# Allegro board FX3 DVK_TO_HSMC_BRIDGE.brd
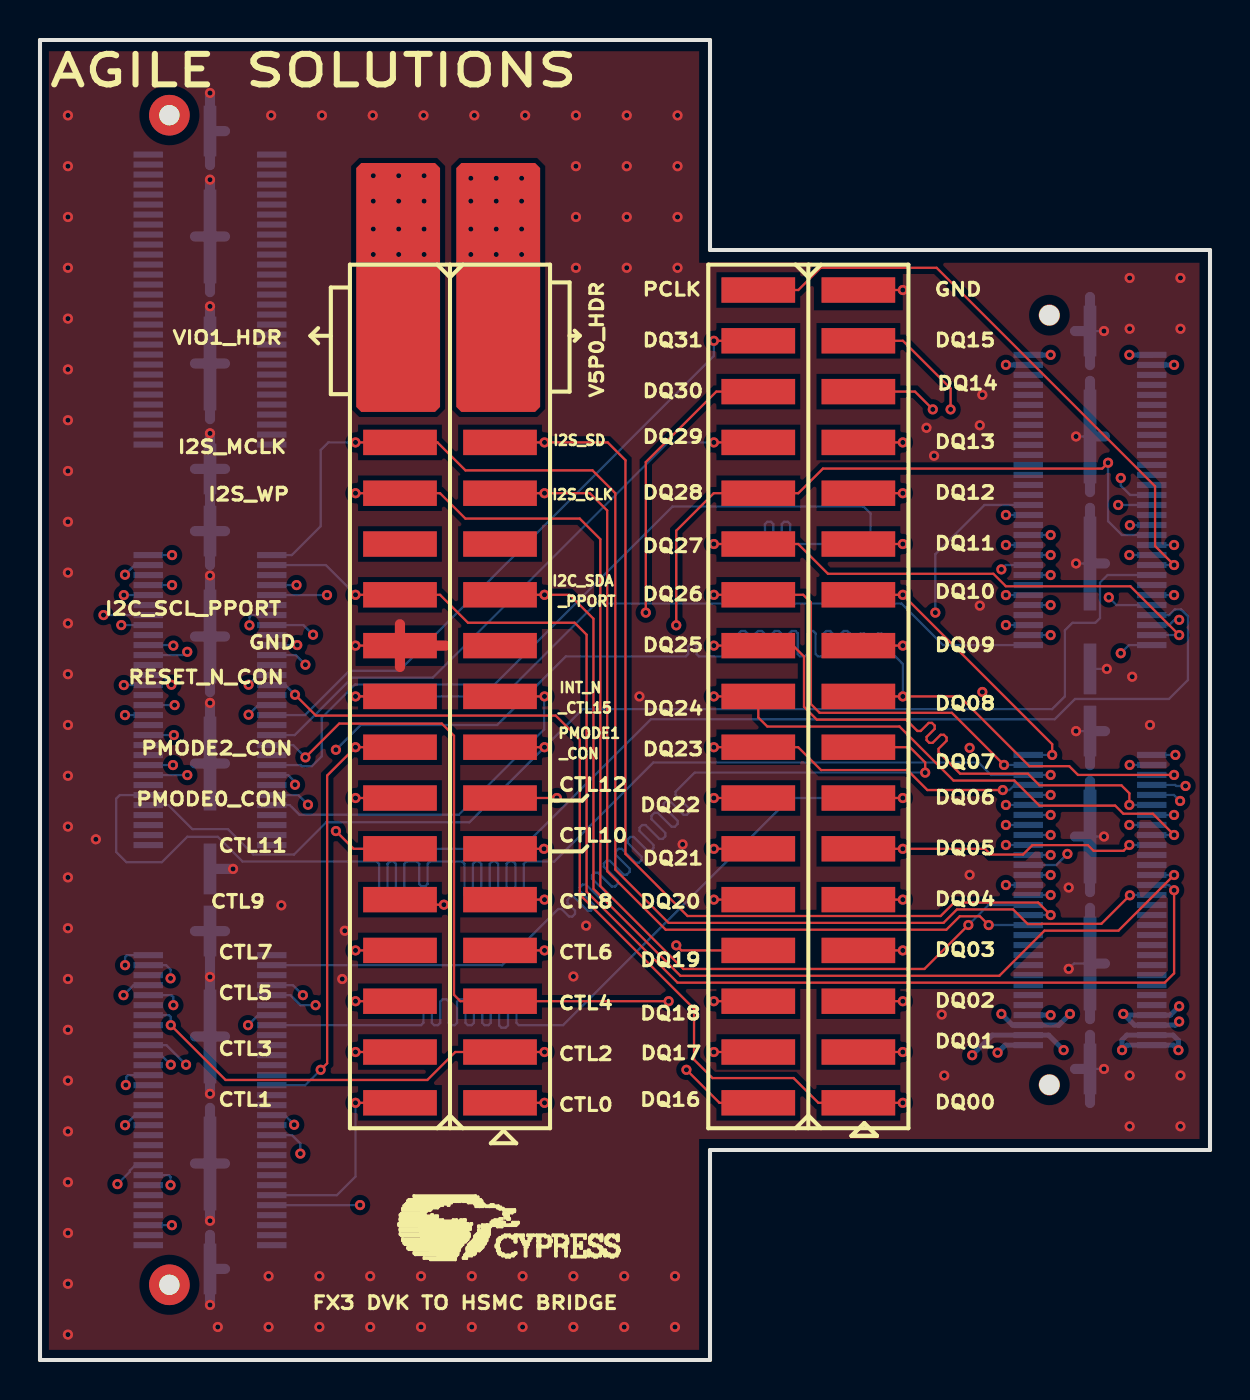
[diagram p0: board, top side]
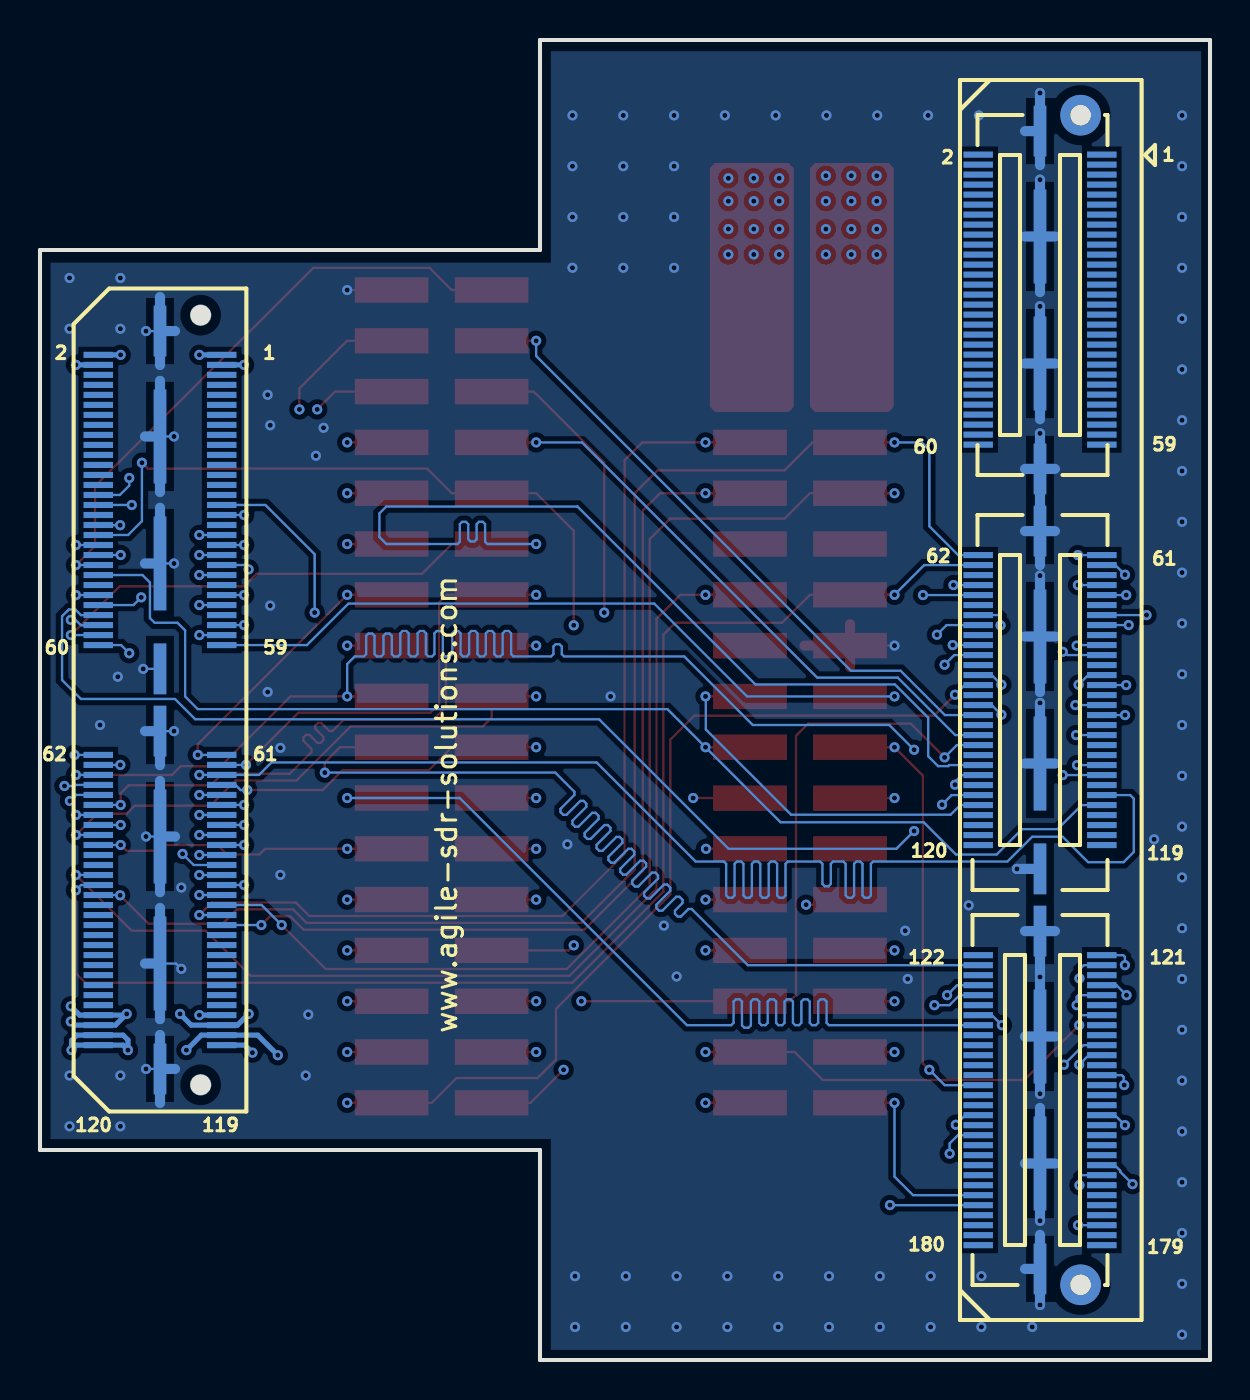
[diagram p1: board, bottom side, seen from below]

Outline 58.5 x 66 mm; copper layers: TOP, L02_GND1, L03_SIG1, L04_SIG2, L05_PWR1, BOTTOM. Coordinates in mm from the lower left corner of the outline.
Outline path: 0,66 0,0 33.5,0 33.5,10.5 58.5,10.5 58.5,55.5 33.5,55.5 33.5,66 0,66

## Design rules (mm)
net group DATA1: nets DQ0 DQ1 DQ2 DQ3 DQ4 DQ5 DQ6 DQ7 DQ8 DQ9 DQ10 DQ11 DQ12 DQ13 DQ14 DQ15 DQ16 DQ17 DQ18 DQ19 DQ20 DQ21 DQ22 DQ23 DQ24 DQ25 DQ26 DQ27 DQ28 DQ29 DQ30 DQ31 PCLK

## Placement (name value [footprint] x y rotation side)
J5  95278-101-34LF  [BERG_2X17_SMD]  38.42 29.37 0 top
J6  95278-101-34LF  [BERG_2X17_SMD]  20.5 29.37 0 top
J7  HSMC CONNECTOR  [CON_180P_19]  8.5 33 270 bottom
J8  QTH120_CONN  [CONN_QTH-060-01-L-D-A]  52.5 33 270 bottom

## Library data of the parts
J5 = HEADER 20x2/SM_1
J6 = HEADER 20x2/SM_0
J7 = HSMC CONNECTOR_0
J8 = QTH120_CONN_3

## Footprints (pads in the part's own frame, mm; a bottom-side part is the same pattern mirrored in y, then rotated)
BERG_2X17_SMD
  rect 3.683x1.27 smd: 1(2.502,-16.51) 2(-2.502,-16.51) 3(2.502,-13.97) 4(-2.502,-13.97) 5(2.502,-11.43) 6(-2.502,-11.43) 7(2.502,-8.89) 8(-2.502,-8.89) 9(2.502,-6.35) 10(-2.502,-6.35) 11(2.502,-3.81) 12(-2.502,-3.81) 13(2.502,-1.27) 14(-2.502,-1.27) 15(2.502,1.27) 16(-2.502,1.27) 17(2.502,3.81) 18(-2.502,3.81) 19(2.502,6.35) 20(-2.502,6.35) 21(2.502,8.89) 22(-2.502,8.89) 23(2.502,11.43) 24(-2.502,11.43) 25(2.502,13.97) 26(-2.502,13.97) 27(2.502,16.51) 28(-2.502,16.51) 29(2.502,19.05) 30(-2.502,19.05) 31(2.502,21.59) 32(-2.502,21.59) 33(2.502,24.13) 34(-2.502,24.13)
CON_180P_19
  round 2.032 hole 1.016 unplated: (-29.24,2.03) (29.24,2.03)
  rect 0.305x1.473 smd: 1(-27.269,3.09) 2(-27.269,-3.09) 3(-26.769,3.09) 4(-26.769,-3.09) 5(-26.269,3.09) 6(-26.269,-3.09) 7(-25.769,3.09) 8(-25.769,-3.09) 9(-25.269,3.09) 10(-25.269,-3.09) 11(-24.769,3.09) 12(-24.769,-3.09) 13(-24.269,3.09) 14(-24.269,-3.09) 15(-23.769,3.09) 16(-23.769,-3.09) 17(-23.269,3.09) 18(-23.269,-3.09) 19(-22.769,3.09) 20(-22.769,-3.09) 21(-22.269,3.09) 22(-22.269,-3.09) 23(-21.769,3.09) 24(-21.769,-3.09) 25(-21.269,3.09) 26(-21.269,-3.09) 27(-20.769,3.09) 28(-20.769,-3.09) 29(-20.269,3.09) 30(-20.269,-3.09) 31(-19.769,3.09) 32(-19.769,-3.09) 33(-19.269,3.09) 34(-19.269,-3.09) 35(-18.769,3.09) 36(-18.769,-3.09) 37(-18.269,3.09) 38(-18.269,-3.09) 39(-17.769,3.09) 40(-17.769,-3.09) 41(-17.269,3.09) 42(-17.269,-3.09) 43(-16.769,3.09) 44(-16.769,-3.09) 45(-16.269,3.09) 46(-16.269,-3.09) 47(-15.769,3.09) 48(-15.769,-3.09) 49(-15.269,3.09) 50(-15.269,-3.09) 51(-14.769,3.09) 52(-14.769,-3.09) 53(-14.269,3.09) 54(-14.269,-3.09) 55(-13.769,3.09) 56(-13.769,-3.09) 57(-13.269,3.09) 58(-13.269,-3.09) 59(-12.769,3.09) 60(-12.769,-3.09) 61(-7.247,3.09) 62(-7.247,-3.09) 63(-6.747,3.09) 64(-6.747,-3.09) 65(-6.247,3.09) 66(-6.247,-3.09) 67(-5.747,3.09) 68(-5.747,-3.09) 69(-5.247,3.09) 70(-5.247,-3.09) 71(-4.747,3.09) 72(-4.747,-3.09) 73(-4.247,3.09) 74(-4.247,-3.09) 75(-3.747,3.09) 76(-3.747,-3.09) 77(-3.247,3.09) 78(-3.247,-3.09) 79(-2.747,3.09) 80(-2.747,-3.09) 81(-2.247,3.09) 82(-2.247,-3.09) 83(-1.747,3.09) 84(-1.747,-3.09) 85(-1.247,3.09) 86(-1.247,-3.09) 87(-0.747,3.09) 88(-0.747,-3.09) 89(-0.247,3.09) 90(-0.247,-3.09) 91(0.253,3.09) 92(0.253,-3.09) 93(0.753,3.09) 94(0.753,-3.09) 95(1.253,3.09) 96(1.253,-3.09) 97(1.753,3.09) 98(1.753,-3.09) 99(2.253,3.09) 100(2.253,-3.09) 101(2.753,3.09) 102(2.753,-3.09) 103(3.253,3.09) 104(3.253,-3.09) 105(3.753,3.09) 106(3.753,-3.09) 107(4.253,3.09) 108(4.253,-3.09) 109(4.753,3.09) 110(4.753,-3.09) 111(5.253,3.09) 112(5.253,-3.09) 113(5.753,3.09) 114(5.753,-3.09) 115(6.253,3.09) 116(6.253,-3.09) 117(6.753,3.09) 118(6.753,-3.09) 119(7.253,3.09) 120(7.253,-3.09) 121(12.758,3.09) 122(12.758,-3.09) 123(13.258,3.09) 124(13.258,-3.09) 125(13.758,3.09) 126(13.758,-3.09) 127(14.258,3.09) 128(14.258,-3.09) 129(14.758,3.09) 130(14.758,-3.09) 131(15.258,3.09) 132(15.258,-3.09) 133(15.758,3.09) 134(15.758,-3.09) 135(16.258,3.09) 136(16.258,-3.09) 137(16.758,3.09) 138(16.758,-3.09) 139(17.258,3.09) 140(17.258,-3.09) 141(17.758,3.09) 142(17.758,-3.09) 143(18.258,3.09) 144(18.258,-3.09) 145(18.758,3.09) 146(18.758,-3.09) 147(19.258,3.09) 148(19.258,-3.09) 149(19.758,3.09) 150(19.758,-3.09) 151(20.258,3.09) 152(20.258,-3.09) 153(20.758,3.09) 154(20.758,-3.09) 155(21.258,3.09) 156(21.258,-3.09) 157(21.758,3.09) 158(21.758,-3.09) 159(22.258,3.09) 160(22.258,-3.09) 161(22.758,3.09) 162(22.758,-3.09) 163(23.258,3.09) 164(23.258,-3.09) 165(23.758,3.09) 166(23.758,-3.09) 167(24.258,3.09) 168(24.258,-3.09) 169(24.758,3.09) 170(24.758,-3.09) 171(25.258,3.09) 172(25.258,-3.09) 173(25.758,3.09) 174(25.758,-3.09) 175(26.258,3.09) 176(26.258,-3.09) 177(26.758,3.09) 178(26.758,-3.09) 179(27.258,3.09) 180(27.258,-3.09)
  rect 4.699x0.635 smd: 181(-16.825,0) 184(-3.175,0) 185(3.175,0) 188(16.825,0) 189(23.175,0) 192(-23.175,0)
  rect 2.54x0.635 smd: 182(-11.555,0) 183(-8.445,0) 186(8.445,0) 187(11.555,0) 190(28.445,0) 191(-28.445,0)
CONN_QTH-060-01-L-D-A
  round 1.067 hole 1.016 unplated: (-19.241,2.032) (19.241,2.032)
  rect 0.305x1.473 smd: 1(-17.257,3.086) 2(-17.257,-3.086) 3(-16.756,3.086) 4(-16.756,-3.086) 5(-16.256,3.086) 6(-16.256,-3.086) 7(-15.756,3.086) 8(-15.756,-3.086) 9(-15.255,3.086) 10(-15.255,-3.086) 11(-14.755,3.086) 12(-14.755,-3.086) 13(-14.255,3.086) 14(-14.255,-3.086) 15(-13.754,3.086) 16(-13.754,-3.086) 17(-13.254,3.086) 18(-13.254,-3.086) 19(-12.753,3.086) 20(-12.753,-3.086) 21(-12.253,3.086) 22(-12.253,-3.086) 23(-11.753,3.086) 24(-11.753,-3.086) 25(-11.252,3.086) 26(-11.252,-3.086) 27(-10.752,3.086) 28(-10.752,-3.086) 29(-10.251,3.086) 30(-10.251,-3.086) 31(-9.751,3.086) 32(-9.751,-3.086) 33(-9.251,3.086) 34(-9.251,-3.086) 35(-8.75,3.086) 36(-8.75,-3.086) 37(-8.25,3.086) 38(-8.25,-3.086) 39(-7.749,3.086) 40(-7.749,-3.086) 41(-7.249,3.086) 42(-7.249,-3.086) 43(-6.749,3.086) 44(-6.749,-3.086) 45(-6.248,3.086) 46(-6.248,-3.086) 47(-5.748,3.086) 48(-5.748,-3.086) 49(-5.248,3.086) 50(-5.248,-3.086) 51(-4.747,3.086) 52(-4.747,-3.086) 53(-4.247,3.086) 54(-4.247,-3.086) 55(-3.747,3.086) 56(-3.747,-3.086) 57(-3.246,3.086) 58(-3.246,-3.086) 59(-2.746,3.086) 60(-2.746,-3.086) 61(2.746,3.086) 62(2.746,-3.086) 63(3.246,3.086) 64(3.246,-3.086) 65(3.747,3.086) 66(3.747,-3.086) 67(4.247,3.086) 68(4.247,-3.086) 69(4.747,3.086) 70(4.747,-3.086) 71(5.248,3.086) 72(5.248,-3.086) 73(5.748,3.086) 74(5.748,-3.086) 75(6.248,3.086) 76(6.248,-3.086) 77(6.749,3.086) 78(6.749,-3.086) 79(7.249,3.086) 80(7.249,-3.086) 81(7.749,3.086) 82(7.749,-3.086) 83(8.25,3.086) 84(8.25,-3.086) 85(8.75,3.086) 86(8.75,-3.086) 87(9.251,3.086) 88(9.251,-3.086) 89(9.751,3.086) 90(9.751,-3.086) 91(10.251,3.086) 92(10.251,-3.086) 93(10.752,3.086) 94(10.752,-3.086) 95(11.252,3.086) 96(11.252,-3.086) 97(11.753,3.086) 98(11.753,-3.086) 99(12.253,3.086) 100(12.253,-3.086) 101(12.753,3.086) 102(12.753,-3.086) 103(13.254,3.086) 104(13.254,-3.086) 105(13.754,3.086) 106(13.754,-3.086) 107(14.255,3.086) 108(14.255,-3.086) 109(14.755,3.086) 110(14.755,-3.086) 111(15.255,3.086) 112(15.255,-3.086) 113(15.756,3.086) 114(15.756,-3.086) 115(16.256,3.086) 116(16.256,-3.086) 117(16.756,3.086) 118(16.756,-3.086) 119(17.257,3.086) 120(17.257,-3.086)
  rect 2.54x0.635 smd: 121(-18.447,0) 124(-1.556,0) 125(1.556,0) 128(18.447,0)
  rect 4.699x0.635 smd: 122(-13.176,0) 123(-6.826,0) 126(6.826,0) 127(13.176,0)

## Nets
GND2: J5.33 J6.20 J7.181 J7.182 J7.183 J7.184 J7.185 J7.186 J7.187 J7.188 J7.189 J7.190 J7.191 J7.192 J8.121 J8.122 J8.123 J8.124 J8.125 J8.126 J8.127 J8.128
V5P0_HDR: J6.29 J6.31 J6.33 J8.113 J8.114 J8.115 J8.116
CTL0: J6.1 J7.158 J8.33
CTL1: J6.2 J7.170 J8.51
CTL2: J6.3 J7.133 J8.55
CTL3: J6.4 J7.154 J8.31
CTL4: J6.5 J7.100 J8.60
CTL5: J6.6 J7.163 J8.39
CTL6: J6.7 J7.141 J8.45
CTL7: J6.8 J7.165 J8.37
CTL8: J6.9 J7.139 J8.49
CTL9: J6.10 J7.153 J8.41
CTL10: J6.11 J7.145 J8.43
CTL11: J6.12 J7.110 J8.54
CTL12: J6.13 J7.129 J8.57
DQ0: J5.1 J7.88 J8.68
DQ1: J5.3 J7.80 J8.74
DQ2: J5.5 J7.76 J8.76
DQ3: J5.7 J7.86 J8.70
DQ4: J5.9 J7.172 J8.50
DQ5: J5.11 J7.70 J8.80
DQ6: J5.13 J7.136 J8.32
DQ7: J5.15 J7.124 J8.42
DQ8: J5.17 J7.92 J8.66
DQ9: J5.19 J7.69 J8.89
DQ10: J5.21 J7.123 J8.61
DQ11: J5.23 J7.85 J8.79
DQ12: J5.25 J7.97 J8.71
DQ13: J5.27 J7.81 J8.81
DQ14: J5.29 J7.109 J8.65
DQ15: J5.31 J7.79 J8.83
DQ16: J5.2 J7.106 J8.56
DQ17: J5.4 J7.75 J8.85
DQ18: J5.6 J7.93 J8.73
DQ19: J5.8 J7.73 J8.87
DQ20: J5.10 J7.87 J8.77
DQ21: J5.12 J7.91 J8.75
DQ22: J5.14 J7.103 J8.69
DQ23: J5.16 J7.105 J8.67
DQ24: J5.18 J7.74 J8.78
DQ25: J5.20 J7.82 J8.72
DQ26: J5.22 J7.121 J8.63
DQ27: J5.24 J7.104 J8.58
DQ28: J5.26 J7.130 J8.38
DQ29: J5.28 J7.98 J8.62
DQ30: J5.30 J7.128 J8.40
DQ31: J5.32 J7.94 J8.64
I2C_SCL_PPORT: J6.22 J7.64 J8.88
I2C_SDA_PPORT: J6.21 J7.68 J8.86
I2S-MCLK: J6.28 J7.62 J8.90
I2S_CLK: J6.25 J7.61 J8.95
I2S_SD: J6.27 J7.63 J8.93
I2S_WP: J6.26 J7.67 J8.91
INT_N_CTL15: J6.17 J7.112 J8.52
PCLK: J5.34 J7.175 J8.44
PMODE0_CON: J6.14 J7.134 J8.36
PMODE1_CON: J6.15 J7.111 J8.46
PMODE2_CON: J6.16 J7.148 J8.30
RESET_N_CON: J6.18 J7.127 J8.59
VIO1_HDR: J6.30 J6.32 J6.34 J8.1 J8.2 J8.3 J8.4 J8.117 J8.118 J8.119 J8.120

Pads without a net: J6 19 23 24; J7 1 2 3 4 5 6 7 8 9 10 11 12 13 14 15 16 17 18 19 20 21 22 23 24 25 26 27 28 29 30 31 32 33 34 35 36 37 38 39 40 41 42 43 44 45 46 47 48 49 50 51 52 53 54 55 56 57 58 59 60 65 66 71 72 77 78 83 84 89 90 95 96 99 101 102 107 108 113 114 115 116 117 118 119 120 122 125 126 131 132 135 137 138 140 142 143 144 146 147 149 150 151 152 155 156 157 159 160 161 162 164 166 167 168 169 171 173 174 176 177 178 179 180; J8 5 6 7 8 9 10 11 12 13 14 15 16 17 18 19 20 21 22 23 24 25 26 27 28 29 34 35 47 48 53 82 84 92 94 96 97 98 99 100 101 102 103 104 105 106 107 108 109 110 111 112

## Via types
v1: diameter 0.508, hole 0.254, TOP to BOTTOM, 308 vias

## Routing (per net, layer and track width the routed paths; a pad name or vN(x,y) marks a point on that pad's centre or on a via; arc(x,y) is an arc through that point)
GND2: length 111.8
  TOP w0.114: J6.20 v1(15.78,35.72) ; J5.33 v1(43.14,53.5)
  TOP w0.508: J6.20 20.27,35.72 ; J6.20 18,34.65 ; J6.20 18,36.79
  BOTTOM w0.114: J8.124 v1(53.34,34.56) ; J8.128 v1(53.2,14.55) ; J8.123 v1(51.8,39.83) ; v1(51.43,19.56) 51.7,19.82 J8.127 ; J8.125 v1(51.8,31.44) ; J8.126 v1(53.2,26.17) ; J8.122 v1(51.8,46.18) ; J8.121 v1(53.2,51.45)
  BOTTOM w0.508: 8.5,59.74 J7.191 ; J7.191 v1(8.5,63.35) ; J7.191 9.25,61.45 ; 7.75,9.82 J7.189 ; J7.189 v1(8.5,6.96) ; J7.189 8.5,12.61 ; J7.189 9.25,9.82 ; 52.5,49.74 J8.121 ; J8.121 51.75,51.45 ; J8.121 52.5,53.15 ; J7.190 9.25,4.55 ; J7.190 8.5,6.26 ; J7.190 v1(8.5,2.75) ; 52.5,23.39 J8.126 ; J8.126 52.5,28.96 ; J8.126 51.75,26.17 ; 52.5,17.04 J8.127 ; J8.127 53.25,19.82 ; J8.127 52.5,22.61 ; 7.75,36.17 J7.184 ; J7.184 8.5,33.39 ; J7.184 9.25,36.17 ; J7.184 v1(8.5,39.22) ; 8.5,53.39 J7.192 ; J7.192 v1(8.5,59.02) ; J7.192 9.25,56.18 ; J7.192 7.75,56.18 ; 7.75,41.45 J7.183 ; J7.183 9.25,41.45 ; J7.183 8.5,39.74 ; J7.183 J7.182 ; 52.5,43.39 J8.122 ; J8.122 52.5,48.96 ; J8.122 53.25,46.18 ; J7.185 v1(8.5,32.85) ; J7.185 9.25,29.82 ; J7.185 7.75,29.82 ; J7.182 9.25,44.56 ; J7.182 v1(8.5,46.33) ; J7.182 7.75,44.56 ; 8.5,47.04 J7.181 ; J7.181 9.25,49.83 ; J7.181 v1(8.5,52.68) ; J7.181 7.75,49.83 ; 51.75,14.55 J8.128 ; J8.128 52.5,16.26 ; J8.128 52.5,12.85 ; 7.75,21.44 J7.187 ; J7.187 9.25,21.44 ; J7.187 v1(8.5,19.15) ; J7.188 9.25,16.17 ; J7.188 8.5,18.96 ; J7.188 7.75,16.17 ; J7.188 v1(8.5,13.31) ; 53.25,39.83 J8.123 52.5,42.61 ; v1(9.65,24.55) J7.186 ; 52.5,29.74 J8.125 53.25,31.44
  vias: v1(1.4,62.23) v1(1.4,59.69) v1(1.4,57.15) v1(1.4,54.61) v1(1.4,52.07) v1(1.4,49.53) v1(1.4,46.99) v1(1.4,44.45) v1(1.4,41.91) v1(1.4,39.37) v1(1.4,36.83) v1(1.4,34.29) v1(1.4,31.75) v1(1.4,29.21) v1(1.4,26.67) v1(1.4,24.13) v1(1.4,21.59) v1(1.4,19.05) v1(1.4,16.51) v1(1.4,13.97) v1(1.4,11.43) v1(1.4,8.89) v1(1.4,6.35) v1(1.4,3.81) v1(1.4,1.27) v1(2.79,26.04) v1(8.89,1.65) v1(11.43,4.19) v1(11.43,1.65) v1(11.56,62.23) v1(12.06,22.73) v1(13.97,4.19) v1(13.97,1.65) v1(14.1,62.23) v1(15.11,19.05) v1(15.24,21.46) v1(16.51,4.19) v1(16.51,1.65) v1(16.64,62.23) v1(19.05,4.19) v1(19.05,1.65) v1(19.18,62.23) v1(21.59,4.19) v1(21.59,1.65) v1(21.72,62.23) v1(24.13,4.19) v1(24.13,1.65) v1(24.26,62.23) v1(26.67,19.18) v1(26.67,4.19) v1(26.67,1.65) v1(26.8,62.23) v1(26.8,59.69) v1(26.8,57.15) v1(26.8,54.61) v1(27.3,21.72) v1(29.21,4.19) v1(29.21,1.65) v1(29.34,62.23) v1(29.34,59.69) v1(29.34,57.15) v1(29.34,54.61) v1(29.97,33.18) v1(31.75,4.19) v1(31.75,1.65) v1(31.88,62.23) v1(31.88,59.69) v1(31.88,57.15) v1(31.88,54.61) v1(32.13,25.78) v1(44.32,46.61) v1(44.7,45.21) v1(45.08,17.27) v1(45.21,14.22) v1(46.48,30.61) v1(46.48,24.26) v1(46.99,46.74) v1(46.99,37.72) v1(47.12,48.26) v1(47.12,33.4) v1(51.43,23.62) v1(54.48,54.1) v1(54.48,51.56) v1(54.48,14.22) v1(54.48,11.68) v1(54.61,34.16) v1(55.5,31.75) v1(57.02,54.1) v1(57.02,51.56) v1(57.02,14.22) v1(57.02,11.68)
V5P0_HDR: length 11
  BOTTOM w0.254: 54.22,17.24 54.73,16.74 J8.116 56.78,16.74 v1(56.96,16.92) ; 54.22,17.24 v1(54.17,17.3) ; 54.22,17.24 J8.114 56.52,17.24 v1(56.96,17.68) ; v1(48.07,17.3) 48.63,16.74 J8.115 50.94,16.74 v1(51.5,17.3) ; J8.113 v1(50.53,17.24)
  vias: v1(21.54,59.09) v1(21.54,57.94) v1(21.54,56.55) v1(21.54,55.28) v1(22.81,59.09) v1(22.81,57.94) v1(22.81,56.55) v1(22.81,55.28) v1(24.08,59.09) v1(24.08,57.94) v1(24.08,56.55) v1(24.08,55.28)
CTL0: length 74.3
  TOP w0.114: J6.1 v1(25.22,12.86)
  L03_SIG1 w0.114: v1(25.22,12.86) 22.68,10.32 v1(13.02,10.32)
  L04_SIG2 w0.114: v1(48.3,42.25) 51.82,42.25 54.38,39.69 54.65,39.69 54.91,39.43 54.91,38.06 53,36.15 52.99,36.15 48.08,31.24 41.24,31.24 39.18,29.17 30.73,29.17 29.65,28.1 29.65,17.29 v1(25.22,12.86)
  BOTTOM w0.114: J7.158 12.6,11.24 13.02,10.83 v1(13.02,10.32) ; J8.33 v1(48.3,42.25)
CTL1: length 65.7
  TOP w0.114: J6.2 v1(15.78,12.86)
  L04_SIG2 w0.114: v1(50.53,37.75) 51.52,36.76 51.52,35.64 48.06,32.18 41.37,32.18 39.05,29.86 30.4,29.86 28.77,28.23 28.77,17.37 24.25,12.86 v1(15.78,12.86)
  BOTTOM w0.114: v1(15.78,12.86) 15.78,9.17 14.85,8.24 J7.170 ; J8.51 v1(50.53,37.75)
CTL2: length 67.1
  TOP w0.114: v1(6.54,16.74) 9.28,14 19.37,14 20.76,15.4 J6.3 v1(25.22,15.4)
  L04_SIG2 w0.114: v1(48.3,36.75) 50.74,36.75 51.18,36.3 51.18,35.78 49.65,34.25 42.82,34.25 38.76,30.2 29.72,30.2 28,28.48 28,18.18 v1(25.22,15.4)
  BOTTOM w0.114: v1(6.54,16.74) 6.54,17.15 6.45,17.24 J7.133 ; J8.55 v1(48.3,36.75)
CTL3: length 61.8
  TOP w0.114: J6.4 v1(15.78,15.4)
  L03_SIG1 w0.114: v1(12.71,11.76) 13,12.05 13,12.08 15.81,14.89 15.81,15.36 v1(15.78,15.4)
  L04_SIG2 w0.114: v1(44.77,37.37) 44.13,36.73 42.23,36.73 38.23,32.74 26.52,32.74 22.54,28.77 22.54,17.44 20.5,15.4 v1(15.78,15.4)
  BOTTOM w0.114: v1(44.77,37.37) 44.77,40.29 47.23,42.75 J8.31 ; J7.154 12.24,12.24 12.51,11.97 12.51,11.96 v1(12.71,11.76)
CTL4: length 71.2
  TOP w0.114: v1(13.27,30.13) 14.96,31.82 20.09,31.82 20.7,31.21 20.7,18.26 21.02,17.94 J6.5 v1(31.43,17.94)
  L04_SIG2 w0.114: v1(54.04,35.34) 53.15,35.34 46.35,28.54 33.46,28.54 30.8,25.87 30.8,18.57 v1(31.43,17.94)
  BOTTOM w0.114: v1(54.04,35.34) 54.45,35.75 J8.60 ; v1(13.27,30.13) 12.66,30.75 J7.100
CTL5: length 67.1
  TOP w0.114: J6.6 v1(15.78,17.94)
  L03_SIG1 w0.114: v1(15.78,17.94) 7.36,9.53 4.6,9.53 v1(3.87,8.79)
  L04_SIG2 w0.114: v1(15.78,17.94) 19.37,21.53 19.37,28.64 25.67,34.94 37.96,34.94 42.7,39.68 45.88,39.68 46.96,40.75 v1(48.3,40.75)
  BOTTOM w0.114: J8.39 v1(48.3,40.75) ; v1(3.87,8.79) 4.49,9.41 4.49,9.47 4.76,9.74 J7.163
CTL6: length 69.3
  TOP w0.114: J6.7 v1(25.22,20.48)
  L03_SIG1 w0.114: v1(6.54,14.76) 6.83,14.47 6.83,14.43 6.93,14.33 10.17,14.33 11.79,15.95 11.79,19.76 15.49,23.46 22.25,23.46 v1(25.22,20.48)
  L04_SIG2 w0.114: v1(50.53,39.25) 50.18,39.25 47.86,36.93 47.86,36.91 45.89,34.94 41.88,34.94 38.66,31.71 28.19,31.71 25.34,28.86 25.34,27.21 26.01,26.54 26.01,21.26 v1(25.22,20.48)
  BOTTOM w0.114: J7.141 6.06,15.24 6.54,14.76 v1(6.54,14.76) ; J8.45 v1(50.53,39.25)
CTL7: length 67.7
  TOP w0.114: J6.8 v1(15.78,20.48)
  L03_SIG1 w0.114: v1(15.78,20.48) 16.26,20 16.26,17.76 7.24,8.74 v1(6.53,8.74)
  L04_SIG2 w0.114: v1(15.78,20.48) 18.99,23.69 18.99,28.89 26.25,36.16 38.7,36.16 42.56,40.02 45.74,40.02 46.91,41.19 48.48,41.19 48.49,41.18 50.46,41.18 v1(50.53,41.25)
  BOTTOM w0.114: J8.37 v1(50.53,41.25) ; v1(6.53,8.74) 6.53,9.15 6.44,9.24 J7.165
CTL8: length 63.6
  TOP w0.114: J6.9 v1(25.22,23.02)
  L03_SIG1 w0.114: v1(25.22,23.02) 24.28,23.96 15.49,23.96 11.44,19.92 11.44,16.11 10.1,14.76 v1(7.3,14.76)
  L04_SIG2 w0.114: v1(25.22,23.02) 25.66,23.46 25.66,26.12 24.96,26.83 24.96,28.96 28.05,32.06 38.52,32.06 41.74,35.28 45.33,35.28 v1(48.3,38.25)
  BOTTOM w0.114: v1(7.3,14.76) 6.32,15.74 J7.139 ; J8.49 v1(48.3,38.25)
CTL9: length 68.6
  TOP w0.114: J6.10 19.49,23.02 19.75,22.76 v1(20.2,22.76)
  L03_SIG1 w0.114: v1(4.25,11.74) 8.19,11.74 12.13,15.68 12.13,19.39 15.51,22.76 v1(20.2,22.76)
  L04_SIG2 w0.114: v1(20.2,22.76) 20.2,28.83 25.81,34.45 38.04,34.45 42.93,39.33 46.02,39.33 47,40.31 50.47,40.31 v1(50.53,40.25)
  BOTTOM w0.114: J7.153 4.75,12.24 v1(4.25,11.74) ; J8.41 v1(50.53,40.25)
CTL10: length 64.8
  TOP w0.114: J6.11 v1(25.2,25.56)
  L03_SIG1 w0.114: v1(25.2,25.56) 16.57,25.56 11.1,20.09 11.1,16.25 10.64,15.8 6.37,15.8 4.62,14.04 4.58,14.04 v1(4.29,13.75)
  L04_SIG2 w0.114: v1(25.2,25.56) 24.57,26.18 24.57,29.07 24.65,29.15 27.9,32.4 38.37,32.4 42.37,36.39 44.94,36.39 48.07,39.52 v1(48.07,39.53)
  BOTTOM w0.114: J7.145 4.4,14.24 4.32,14.15 4.32,13.77 v1(4.29,13.75) ; v1(48.07,39.53) 48.29,39.75 J8.43
CTL11: length 59.2
  TOP w0.114: J6.12 15.68,25.56 v1(14.8,26.45)
  L03_SIG1 w0.114: v1(14.8,26.45) 14.71,26.45 v1(13.4,27.76)
  BOTTOM w0.114: v1(14.8,26.45) 15.68,25.56 24.07,25.56 30.54,32.04 50.74,32.04 51.75,33.05 56.45,33.05 57.4,34 57.4,37.19 57.14,37.45 57.14,37.45 57.06,37.53 56.74,37.53 56.45,37.24 55.59,37.24 J8.54 ; v1(13.4,27.76) 12.92,28.25 J7.110
CTL12: length 59.9
  TOP w0.114: J6.13 v1(25.84,28.1)
  L03_SIG1 w0.114: v1(6.67,17.74) 6.67,18.48 12.32,24.13 13.84,24.13 15.23,25.52 15.23,28.18 15.59,28.54 25.41,28.54 v1(25.84,28.1)
  L04_SIG2 w0.114: v1(25.84,28.1) 25.84,28.72 28.49,31.37 38.8,31.37 42.03,34.6 48.72,34.6 50.37,36.25 v1(50.53,36.25)
  BOTTOM w0.114: v1(6.67,17.74) 6.67,18.15 6.58,18.24 J7.129 ; J8.57 v1(50.53,36.25)
DQ0: length 75.9
  TOP w0.114: v1(12.75,33.26) 13.79,32.22 25.79,32.22 26.99,31.02 26.99,23.27 32.7,17.56 32.7,15.02 33.62,14.1 37.68,14.1 38.92,12.86 J5.1 v1(43.14,12.86)
  L04_SIG2 w0.114: v1(57.28,28.7) 57.59,28.38 57.59,22.58 57.48,22.46 56.88,22.46 56.77,22.35 56.77,22.16 56.88,22.04 57.48,22.04 57.59,21.93 57.59,19.37 54.74,16.51 50.29,16.51 46.64,12.86 v1(43.14,12.86)
  BOTTOM w0.114: J8.68 56.77,28.75 56.82,28.7 v1(57.28,28.7) ; J7.88 12.27,33.75 v1(12.75,33.26)
DQ1: length 77.7
  TOP w0.114: J5.3 v1(43.14,15.4)
  L03_SIG1 w0.114: v1(12.86,35.75) 12.86,36.45 13.24,36.83 26.99,36.83 27.11,36.94 27.11,37.6 27.22,37.72 27.41,37.72 27.53,37.6 27.53,36.94 27.64,36.83 30.89,36.83 31.39,37.34 34.2,37.34 34.71,36.83 38.35,36.83 42.04,33.15 42.04,25.96 44.27,23.73 44.27,16.52 v1(43.14,15.4)
  L04_SIG2 w0.114: v1(56.7,27.25) 55.4,25.95 55.4,22.5 51.17,18.28 48.26,18.28 45.38,15.4 v1(43.14,15.4)
  BOTTOM w0.114: J8.74 v1(56.7,27.25) ; J7.80 v1(12.86,35.75)
DQ2: length 77.8
  TOP w0.114: J5.5 v1(43.14,17.94)
  L03_SIG1 w0.114: v1(13.65,36.26) 33.77,36.26 36.77,33.27 36.77,30.74 43.92,23.59 43.92,18.72 v1(43.14,17.94)
  L04_SIG2 w0.114: v1(43.14,17.94) 43.14,19.56 43.65,20.07 44.1,20.07 44.22,19.95 44.22,18.15 44.33,18.03 44.52,18.03 44.64,18.15 44.64,19.95 44.75,20.07 44.94,20.07 45.06,19.95 45.06,18.15 45.17,18.03 45.36,18.03 45.48,18.15 45.48,19.95 45.59,20.07 45.79,20.07 45.9,19.95 45.9,18.15 46.01,18.03 46.21,18.03 46.32,18.15 46.32,19.95 46.43,20.07 51.12,20.07 53.98,22.92 53.98,26.26 v1(54.47,26.75)
  BOTTOM w0.114: J7.76 13.17,36.75 v1(13.65,36.26) ; J8.76 v1(54.47,26.75)
DQ3: length 78
  TOP w0.114: J5.7 v1(43.14,20.48)
  L03_SIG1 w0.114: v1(43.14,20.48) 43.58,20.92 43.58,23.44 43.15,23.88 42.42,23.88 42.16,23.62 42.16,22.73 41.78,22.35 39.5,22.35 39.23,22.62 39.23,23.71 39.35,23.82 40.53,23.82 40.64,23.94 40.64,24.13 40.53,24.24 39.35,24.24 39.23,24.36 39.23,24.55 39.35,24.66 40.53,24.66 40.64,24.78 40.64,24.97 40.53,25.08 39.35,25.08 39.23,25.2 39.23,25.39 39.35,25.5 40.53,25.5 40.64,25.62 40.64,25.81 40.53,25.93 39.35,25.93 39.23,26.04 39.23,27.55 35.25,31.53 33.41,31.53 31.18,33.76 v1(10.43,33.76)
  L04_SIG2 w0.114: v1(43.14,20.48) 51.05,20.48 53.64,23.06 53.64,27.7 54.29,28.35 56.59,28.35 56.99,27.95 v1(57.01,27.95)
  BOTTOM w0.114: J7.86 10.91,34.25 v1(10.43,33.76) ; v1(57.01,27.95) 56.99,27.95 56.69,28.25 J8.70
DQ4: length 78.2
  TOP w0.114: J5.9 v1(43.14,23.02)
  L03_SIG1 w0.114: v1(43.14,23.02) 42.42,22.3 42.42,20.76 42.3,20.65 41.26,20.65 41.15,20.53 41.15,20.34 41.26,20.22 42.43,20.22 42.54,20.11 42.54,19.92 42.43,19.8 41.26,19.8 41.15,19.69 41.15,19.5 41.26,19.38 42.3,19.38 42.42,19.27 42.42,19.08 42.3,18.96 41.26,18.96 41.15,18.85 41.15,18.66 41.26,18.54 42.3,18.54 42.42,18.43 42.42,13.82 41.93,13.34 28.7,13.34 23.11,7.75 v1(16,7.75)
  L04_SIG2 w0.114: v1(56.7,38.25) 56.13,37.68 56.13,34.8 52.13,30.8 52.13,25.1 51.85,24.81 44.93,24.81 v1(43.14,23.02)
  BOTTOM w0.114: v1(16,7.75) 16,7.74 J7.172 ; J8.50 v1(56.7,38.25)
DQ5: length 78.1
  TOP w0.114: v1(54.47,25.75) 54.18,25.46 52.68,25.46 52.4,25.74 49.62,25.74 49.15,25.27 47.54,25.27 47.25,25.56 v1(43.14,25.56) J5.11
  L03_SIG1 w0.114: v1(43.14,25.56) 42.42,26.28 42.42,35.31 42.01,35.71 41.85,35.71 41.13,34.98 40.96,34.98 40.83,35.12 40.83,35.28 41.56,36.01 41.56,36.17 41.42,36.3 41.26,36.3 40.53,35.58 40.37,35.58 40.23,35.71 40.23,35.87 40.96,36.6 40.96,36.76 40.83,36.9 40.66,36.9 39.94,36.17 39.77,36.17 39.64,36.31 39.64,36.47 40.37,37.2 40.37,37.36 40.23,37.49 40.07,37.49 39.34,36.77 39.18,36.77 39.04,36.9 39.04,37.06 39.77,37.79 39.77,37.95 39.64,38.09 39.47,38.09 38.75,37.36 38.58,37.36 38.45,37.5 38.45,37.66 39.18,38.39 39.18,38.55 38.86,38.86 37.84,38.86 37.73,38.75 37.73,37.58 37.61,37.47 37.42,37.47 37.31,37.58 37.31,38.75 37.19,38.86 37,38.86 36.88,38.75 36.88,37.58 36.77,37.47 36.58,37.47 36.46,37.58 36.46,38.75 36.35,38.86 36.16,38.86 36.04,38.75 36.04,37.58 35.93,37.47 35.74,37.47 35.62,37.58 35.62,38.75 35.51,38.86 35.23,38.86 35.12,38.75 35.12,38.34 35,38.23 34.81,38.23 34.69,38.34 34.69,38.75 34.58,38.86 27.05,38.86 25.87,37.68 14.92,37.68 v1(14.35,38.25)
  BOTTOM w0.114: J7.70 v1(14.35,38.25) ; J8.80 v1(54.47,25.75)
DQ6: length 78.1
  TOP w0.114: J5.13 v1(43.14,28.1)
  L04_SIG2 w0.114: v1(43.14,28.1) 46.64,28.1 47.62,29.08 48.64,29.08 55.69,36.13 55.69,40.04 55.04,40.69 54.43,40.69 53.71,41.4 53.71,42.55 v1(53.91,42.75)
  BOTTOM w0.114: v1(43.14,28.1) 37.51,28.1 26.15,16.74 23.94,16.74 23.82,16.86 23.82,17.92 23.71,18.03 23.52,18.03 23.4,17.92 23.4,16.73 23.29,16.61 23.07,16.61 22.96,16.73 22.96,17.92 22.84,18.03 22.65,18.03 22.54,17.92 22.54,16.86 22.42,16.74 22.23,16.74 22.11,16.86 22.11,17.92 22,18.03 21.81,18.03 21.69,17.92 21.69,16.86 21.58,16.74 21.39,16.74 21.27,16.86 21.27,17.92 21.16,18.03 20.97,18.03 20.85,17.92 20.85,16.86 20.74,16.74 20.55,16.74 20.43,16.86 20.43,17.92 20.32,18.03 20.13,18.03 20.01,17.92 20.01,16.86 19.9,16.74 19.71,16.74 19.59,16.86 19.59,17.92 19.48,18.03 19.28,18.03 19.17,17.92 19.17,16.86 19.06,16.74 J7.136 ; J8.32 v1(53.91,42.75)
DQ7: length 80.1
  TOP w0.114: v1(44.26,29.37) 44.26,29.88 43.5,30.64 J5.15
  L04_SIG2 w0.114: v1(44.26,29.37) 46.7,29.37 53.13,35.81 53.14,35.81 54.16,36.83 55.25,37.92 55.25,39.91 54.91,40.25 v1(54.47,40.25)
  BOTTOM w0.114: v1(44.26,29.37) 32.73,29.37 31.78,28.41 31.78,28.25 32.47,27.56 32.47,27.4 32.34,27.26 32.18,27.26 31.48,27.96 31.32,27.96 31.18,27.82 31.18,27.66 31.88,26.96 31.88,26.8 31.74,26.66 31.58,26.66 30.89,27.36 30.72,27.36 30.57,27.21 30.57,27.05 31.27,26.35 31.27,26.19 31.13,26.05 30.97,26.05 30.27,26.75 30.11,26.75 29.98,26.61 29.98,26.45 30.67,25.75 30.67,25.59 30.54,25.46 30.38,25.46 29.68,26.15 29.52,26.15 29.38,26.02 29.38,25.86 30.08,25.16 30.08,25 29.94,24.86 29.78,24.86 29.08,25.56 28.92,25.56 28.79,25.42 28.79,25.26 29.48,24.57 29.48,24.4 29.35,24.27 29.19,24.27 28.49,24.96 28.33,24.96 28.19,24.83 28.19,24.67 28.89,23.97 28.89,23.81 28.75,23.67 28.59,23.67 27.9,24.37 27.73,24.37 27.6,24.23 27.6,24.07 28.29,23.38 28.29,23.21 28.16,23.08 28,23.08 27.3,23.77 27.14,23.77 26.99,23.62 26.99,23.46 27.68,22.76 27.68,22.6 27.55,22.47 27.38,22.47 26.69,23.16 26.53,23.16 26.37,23.01 26.37,22.85 26.75,22.47 26.75,22.31 26.62,22.17 26.45,22.17 26.08,22.55 25.91,22.55 23.11,19.74 J7.124 ; J8.42 v1(54.47,40.25)
DQ8: length 77.9
  TOP w0.114: J5.17 v1(43.14,33.18) 45.98,33.18 49.47,29.69 51.46,29.69 51.9,29.25 v1(56.7,29.25)
  L04_SIG2 w0.114: v1(14.8,30.51) 14.26,31.05 11.65,31.05 v1(10.43,32.26)
  BOTTOM w0.114: v1(10.43,32.26) 10.91,32.75 J7.92 ; v1(43.14,33.18) 43.14,34.8 42.76,35.18 42.31,35.18 42.19,35.29 42.19,36.21 42.08,36.32 41.89,36.32 41.77,36.21 41.77,35.29 41.66,35.18 41.44,35.18 41.33,35.29 41.33,36.21 41.21,36.32 41.02,36.32 40.91,36.21 40.91,35.29 40.79,35.18 40.6,35.18 40.49,35.29 40.49,36.33 40.37,36.45 40.18,36.45 40.07,36.33 40.07,35.29 39.95,35.18 39.74,35.18 39.62,35.29 39.62,36.33 39.51,36.45 39.31,36.45 39.2,36.33 39.2,35.29 39.09,35.18 38.89,35.18 38.78,35.29 38.78,36.33 38.67,36.45 38.47,36.45 38.36,36.33 38.36,35.29 38.24,35.18 38,35.18 37.89,35.29 37.89,36.33 37.78,36.45 37.58,36.45 37.47,36.33 37.47,35.29 37.35,35.18 37.16,35.18 37.05,35.29 37.05,36.33 36.93,36.45 36.74,36.45 36.63,36.33 36.63,35.29 36.51,35.18 36.32,35.18 36.21,35.29 36.21,36.33 36.09,36.45 35.9,36.45 35.79,36.33 35.79,35.29 35.67,35.18 35.48,35.18 35.37,35.29 35.37,36.33 35.25,36.45 35.06,36.45 34.95,36.33 34.95,35.29 34.83,35.18 32.94,35.18 32.83,35.29 32.83,35.67 32.72,35.79 32.52,35.79 32.41,35.67 32.41,35.29 32.3,35.18 26.29,35.18 22.86,31.75 16.03,31.75 v1(14.8,30.51) ; J8.66 v1(56.7,29.25)
DQ9: length 78.2
  TOP w0.114: J5.19 v1(43.14,35.72)
  L03_SIG1 w0.114: v1(50.53,23.25) 50.12,23.25 50.09,23.27 45.31,23.27 44.89,23.69 44.89,35.37 44.54,35.72 v1(43.14,35.72) 43.14,37.38 40.88,39.64 37.08,39.64 36.97,39.76 36.97,40.53 36.85,40.64 36.66,40.64 36.55,40.53 36.55,39.76 36.43,39.64 36.24,39.64 36.13,39.76 36.13,40.65 36.01,40.77 35.82,40.77 35.71,40.65 35.71,39.76 35.59,39.64 35.4,39.64 35.29,39.76 35.29,40.65 35.17,40.77 34.98,40.77 34.87,40.65 34.87,39.76 34.75,39.64 12.7,39.64 8.53,35.47 8.53,34.57 7.24,33.27 6.1,33.27 5.27,34.1 5.27,37.17 v1(4.19,38.25)
  BOTTOM w0.114: J8.89 v1(50.53,23.25) ; J7.69 v1(4.19,38.25)
DQ10: length 78.1
  TOP w0.114: v1(50.61,30.25) 50.61,30.79 v1(43.14,38.26) J5.21
  L04_SIG2 w0.114: v1(43.14,38.26) 43.12,38.26 38.47,33.62 26.54,33.62 21.53,28.61 21.53,17.62 21.08,17.18 12.92,17.18 12.45,17.65 12.45,20.74 12.1,21.08 10.89,21.08 10.77,21.2 10.77,21.86 10.66,21.97 10.47,21.97 10.35,21.86 10.35,21.07 10.24,20.95 10.02,20.95 9.91,21.07 9.91,21.86 9.79,21.97 9.6,21.97 9.49,21.86 9.49,21.07 9.37,20.95 9.18,20.95 9.07,21.07 9.07,21.86 8.95,21.97 8.76,21.97 8.64,21.86 8.64,21.2 8.53,21.08 6.98,21.08 6.53,20.62 v1(6.53,19.08)
  BOTTOM w0.114: v1(6.53,19.08) 6.53,19.52 6.31,19.74 J7.123 ; J8.61 v1(50.61,30.25)
DQ11: length 78.3
  TOP w0.114: J5.23 v1(43.14,40.8)
  L03_SIG1 w0.114: v1(6.57,33.76) 8.19,35.38 8.19,35.62 12.63,40.05 31.29,40.05 33.78,42.55 38.82,42.55 38.93,42.66 38.93,44.08 39.05,44.2 39.24,44.2 39.35,44.08 39.35,42.66 39.47,42.55 39.66,42.55 39.77,42.66 39.77,44.08 39.89,44.2 40.08,44.2 40.19,44.08 40.19,42.66 40.31,42.55 40.5,42.55 40.61,42.66 40.61,44.08 40.73,44.2 40.92,44.2 41.04,44.08 41.04,42.66 41.15,42.55 41.34,42.55 41.46,42.66 41.46,44.08 41.57,44.2 41.76,44.2 41.88,44.08 41.88,42.66 41.99,42.55 42.8,42.55 43.14,42.2 v1(43.14,40.8) 44.58,40.8 45.28,40.1 45.28,26.1 45.62,25.75 v1(48.3,25.75)
  BOTTOM w0.114: J8.79 v1(48.3,25.75) ; v1(6.57,33.76) 6.09,34.25 J7.85
DQ12: length 77.9
  TOP w0.114: J5.25 v1(43.14,43.34)
  L03_SIG1 w0.114: v1(43.14,43.34) 45.78,40.7 45.78,28.35 46.42,27.72 48.26,27.72 v1(48.3,27.75)
  L04_SIG2 w0.114: v1(43.14,43.34) 41.78,43.34 41.66,43.45 41.66,44.34 41.55,44.45 41.36,44.45 41.24,44.34 41.24,43.33 41.13,43.21 40.94,43.21 40.82,43.33 40.82,44.34 40.71,44.45 40.52,44.45 40.4,44.34 40.4,43.33 40.29,43.21 40.1,43.21 39.98,43.33 39.98,44.34 39.87,44.45 39.68,44.45 39.56,44.34 39.56,43.33 39.45,43.21 39.25,43.21 39.14,43.33 39.14,44.34 39.03,44.45 38.83,44.45 38.72,44.34 38.72,43.45 38.61,43.34 38.41,43.34 38.3,43.45 38.3,44.34 38.18,44.45 37.99,44.45 37.88,44.34 37.88,43.45 37.76,43.34 37.57,43.34 37.46,43.45 37.46,44.34 37.34,44.45 37.15,44.45 37.04,44.34 37.04,43.45 36.92,43.34 27.11,43.34 16.07,32.29 11.24,32.29 10.73,32.8 9.21,32.8 7.66,31.25 v1(6.69,31.25)
  BOTTOM w0.114: J8.71 v1(48.3,27.75) ; J7.97 v1(6.69,31.25)
DQ13: length 77.9
  TOP w0.114: J5.27 v1(43.14,45.88)
  L03_SIG1 w0.114: v1(7.36,35.41) 12.37,40.42 30.64,40.42 36.1,45.88 v1(43.14,45.88) 45.72,45.88 46.33,45.27 46.33,42.98 46.44,42.87 47.26,42.87 47.37,42.75 47.37,42.56 47.26,42.45 46.44,42.45 46.33,42.33 46.33,42.14 46.44,42.03 47.26,42.03 47.37,41.91 47.37,41.72 47.26,41.61 46.44,41.61 46.33,41.49 46.33,41.3 46.44,41.19 47.13,41.19 47.24,41.07 47.24,40.88 47.13,40.76 46.44,40.76 46.33,40.65 46.33,40.46 46.44,40.34 47.13,40.34 47.24,40.23 47.24,40.04 47.13,39.92 46.44,39.92 46.33,39.81 46.33,32.79 49.34,29.78 49.34,25.59 49.68,25.25 v1(50.53,25.25)
  BOTTOM w0.114: v1(7.36,35.41) 7.28,35.41 7.12,35.25 J7.81 ; J8.81 v1(50.53,25.25)
DQ14: length 101.8
  TOP w0.114: J5.29 43.75,48.42 v1(44.64,47.53)
  L03_SIG1 w0.114: v1(50.53,29.25) 49.97,29.81 49.97,42.2 v1(44.64,47.53)
  BOTTOM w0.114: J7.109 3.99,28.25 3.81,28.07 3.81,25.4 4.32,24.89 6.1,24.89 7.37,26.16 8.89,26.16 10.13,24.92 16.84,24.92 16.96,24.81 16.96,23.23 17.07,23.11 17.26,23.11 17.38,23.23 17.38,24.81 17.49,24.92 17.68,24.92 17.8,24.81 17.8,23.23 17.91,23.11 18.1,23.11 18.22,23.23 18.22,24.81 18.33,24.92 18.84,24.92 18.96,24.81 18.96,23.8 19.07,23.69 19.27,23.69 19.38,23.8 19.38,24.81 19.49,24.92 21.11,24.92 21.22,24.81 21.22,23.23 21.34,23.11 21.53,23.11 21.64,23.23 21.64,24.81 21.76,24.92 21.95,24.92 22.07,24.81 22.07,23.23 22.18,23.11 22.37,23.11 22.49,23.23 22.49,24.81 22.6,24.92 22.79,24.92 22.91,24.81 22.91,23.23 23.02,23.11 23.21,23.11 23.33,23.23 23.33,24.81 23.44,24.92 23.66,24.92 23.77,24.81 23.77,23.23 23.89,23.11 24.08,23.11 24.19,23.23 24.19,24.81 24.31,24.92 25.72,24.92 30.67,29.88 46.93,29.88 47.55,29.25 J8.65 v1(50.53,29.25)
DQ15: length 82
  TOP w0.114: J5.31 43.15,50.96 45.53,48.58 v1(45.53,47.53)
  L03_SIG1 w0.114: v1(51.37,25.3) 51.37,30.54 51.18,30.73 51.18,47.12 50.77,47.53 v1(45.53,47.53) 45.02,48.04 37.15,48.04 29.91,40.8 11.75,40.8 v1(6.67,35.72)
  BOTTOM w0.114: v1(6.67,35.72) 6.64,35.75 J7.79 ; J8.83 50.82,24.75 v1(51.37,25.3)
DQ16: length 79.7
  TOP w0.114: J5.2 33.97,12.86 v1(32.32,14.51)
  L03_SIG1 w0.114: v1(12.75,28.76) 14.48,28.76 14.93,29.22 25.86,29.22 32.25,22.83 32.25,14.44 32.32,14.37 v1(32.32,14.51)
  L04_SIG2 w0.114: v1(56.96,37.01) 56.51,36.56 56.51,34.29 52.51,30.29 52.51,22.43 51.33,21.24 43.28,21.24 38.58,16.54 38.58,16.37 39.08,15.87 39.08,15.71 38.94,15.58 38.78,15.58 38.28,16.08 38.12,16.08 36.55,14.51 v1(32.32,14.51)
  BOTTOM w0.114: J7.106 12.41,29.25 12.75,28.9 v1(12.75,28.76) ; v1(56.96,37.01) 56.94,36.99 56.71,36.99 56.45,36.74 55.59,36.74 J8.56
DQ17: length 77.7
  TOP w0.114: J5.4 v1(33.69,15.4)
  L03_SIG1 w0.114: v1(4.06,36.75) 2.41,35.1 2.41,27.18 2.79,26.8 10.03,26.8 12.59,29.35 14.36,29.35 14.57,29.57 26.03,29.57 32.64,22.96 32.64,16.45 v1(33.69,15.4)
  L04_SIG2 w0.114: v1(50.53,24.25) 49.3,23.02 44.58,23.02 36.96,15.4 v1(33.69,15.4)
  BOTTOM w0.114: v1(4.06,36.75) J7.75 ; J8.85 v1(50.53,24.25)
DQ18: length 77.6
  TOP w0.114: J5.6 v1(33.69,17.94)
  L03_SIG1 w0.114: v1(33.69,17.94) 33.02,18.61 33.02,20.21 33.13,20.32 34.05,20.32 34.16,20.43 34.16,20.63 34.05,20.74 33.13,20.74 33.02,20.85 33.02,21.05 33.13,21.16 34.05,21.16 34.16,21.28 34.16,21.47 34.05,21.58 33.13,21.58 33.02,21.7 33.02,23.08 26.19,29.91 14.43,29.91 14.21,29.69 11.94,29.69 9.83,27.59 5.52,27.59 4.25,28.87 v1(4.25,32.25)
  L04_SIG2 w0.114: v1(50.53,27.25) 49.59,26.31 35.43,26.31 31.37,22.26 31.37,19.14 32.58,17.94 v1(33.69,17.94)
  BOTTOM w0.114: J7.93 v1(4.25,32.25) ; J8.73 v1(50.53,27.25)
DQ19: length 79.9
  TOP w0.114: v1(31.81,20.73) 32.07,20.48 J5.8
  L03_SIG1 w0.114: v1(3.17,37.25) 2.03,36.1 2.03,25.53 2.41,25.15 3.34,25.15 3.46,25.03 3.46,24.24 3.57,24.13 3.76,24.13 3.88,24.24 3.88,25.03 3.99,25.15 4.18,25.15 4.3,25.03 4.3,24.24 4.41,24.13 4.61,24.13 4.72,24.24 4.72,25.03 4.83,25.15 9.91,25.15 13.11,28.35 14.93,28.35 15.45,28.88 25.68,28.88 26.58,27.98 26.58,21.17 27.02,20.73 v1(31.81,20.73)
  L04_SIG2 w0.114: v1(48.3,23.75) 44.82,23.75 41.81,20.73 v1(31.81,20.73)
  BOTTOM w0.114: J8.87 v1(48.3,23.75) ; J7.73 v1(3.17,37.25)
DQ20: length 77.9
  TOP w0.114: J5.10 v1(33.69,23.02)
  L03_SIG1 w0.114: v1(33.69,23.02) 34.64,23.02 35.05,22.61 35.05,19.3 35.31,19.05 35.94,19.05 36.19,19.3 36.19,24.51 35.72,24.99 34.38,24.99 34.27,24.88 34.27,24.24 34.15,24.13 33.96,24.13 33.85,24.24 33.85,24.88 33.73,24.99 33.54,24.99 33.43,24.88 33.43,24.24 33.31,24.13 33.12,24.13 33.01,24.24 33.01,24.88 32.89,24.99 31.72,24.99 25.63,31.08 12.84,31.08 9.69,27.93 5.82,27.93 4.95,28.8 4.95,32.98 v1(4.19,33.75)
  L04_SIG2 w0.114: v1(33.69,23.02) 41.56,23.02 43.85,25.31 49.59,25.31 v1(50.53,26.25)
  BOTTOM w0.114: J8.77 v1(50.53,26.25) ; J7.87 v1(4.19,33.75)
DQ21: length 78.3
  TOP w0.114: J5.12 v1(33.69,25.56)
  L03_SIG1 w0.114: v1(33.69,25.56) 33,26.25 33,26.41 33.8,27.21 33.8,27.37 33.67,27.51 33.5,27.51 32.58,26.58 32.42,26.58 32.28,26.72 32.28,26.88 33.21,27.8 33.21,27.97 33.07,28.1 32.91,28.1 32.11,27.3 31.95,27.3 31.7,27.55 31.7,27.71 32.95,28.96 32.95,29.12 32.81,29.26 32.65,29.26 31.41,28.01 31.24,28.01 31.11,28.14 31.11,28.31 31.97,29.17 31.97,29.33 31.84,29.47 31.68,29.47 30.81,28.6 30.65,28.6 30.51,28.74 30.51,28.9 31.38,29.77 31.38,29.93 31.24,30.06 31.08,30.06 30.22,29.2 30.05,29.2 29.92,29.33 29.92,29.5 30.78,30.36 30.78,30.52 30.65,30.66 30.49,30.66 29.62,29.79 29.46,29.79 29.32,29.93 29.32,30.09 30.19,30.96 30.19,31.12 30.05,31.25 29.89,31.25 29.03,30.39 28.86,30.39 28.73,30.52 28.73,30.68 29.59,31.55 29.59,31.71 29.46,31.85 29.3,31.85 28.43,30.98 28.27,30.98 27.83,31.42 12.69,31.42 9.63,28.35 6.16,28.35 5.59,28.92 5.59,31.6 v1(6.73,32.75)
  L04_SIG2 w0.114: v1(48.3,26.75) 34.89,26.75 v1(33.69,25.56)
  BOTTOM w0.114: J7.91 v1(6.73,32.75) ; J8.75 v1(48.3,26.75)
DQ22: length 78.3
  TOP w0.114: J5.14 v1(33.69,28.1)
  L03_SIG1 w0.114: v1(33.69,28.1) 36.58,25.22 36.58,21.84 36.83,21.59 38.35,21.59 38.73,21.97 38.73,23.58 38.62,23.69 37.58,23.69 37.46,23.81 37.46,24 37.58,24.11 38.62,24.11 38.73,24.23 38.73,24.42 38.62,24.53 37.58,24.53 37.46,24.65 37.46,24.84 37.58,24.95 38.62,24.95 38.73,25.07 38.73,27.18 35.94,29.97 31.82,29.97 29.41,32.38 12.97,32.38 9.28,28.7 7.09,28.7 6.65,29.13 v1(6.65,29.75)
  L04_SIG2 w0.114: v1(50.53,28.25) 49.59,27.31 34.48,27.31 v1(33.69,28.1)
  BOTTOM w0.114: J8.69 v1(50.53,28.25) ; v1(6.65,29.75) J7.103
DQ23: length 75.6
  TOP w0.114: v1(48.14,28.5) 44.37,28.5 43.37,29.5 39.05,29.5 37.91,30.64 J5.16 v1(33.69,30.64)
  L03_SIG1 w0.114: v1(33.69,30.64) 31.6,32.73 28.57,32.73 28.45,32.84 28.45,33.29 28.34,33.4 28.15,33.4 28.03,33.29 28.03,32.84 27.92,32.73 27.73,32.73 27.61,32.84 27.61,33.29 27.5,33.4 27.31,33.4 27.19,33.29 27.19,32.84 27.08,32.73 26.89,32.73 26.77,32.84 26.77,33.29 26.66,33.4 26.47,33.4 26.35,33.29 26.35,32.84 26.24,32.73 24.5,32.73 24.39,32.84 24.39,33.29 24.27,33.4 24.08,33.4 23.97,33.29 23.97,32.84 23.85,32.73 23.66,32.73 23.55,32.84 23.55,33.29 23.43,33.4 23.24,33.4 23.13,33.29 23.13,32.84 23.01,32.73 22.82,32.73 22.71,32.84 22.71,33.29 22.59,33.4 22.4,33.4 22.29,33.29 22.29,32.84 22.17,32.73 21.98,32.73 21.87,32.84 21.87,33.29 21.75,33.4 21.56,33.4 21.44,33.29 21.44,32.84 21.33,32.73 21.14,32.73 21.02,32.84 21.02,33.29 20.91,33.4 20.72,33.4 20.6,33.29 20.6,32.84 20.49,32.73 20.3,32.73 20.18,32.84 20.18,33.29 20.07,33.4 19.88,33.4 19.76,33.29 19.76,32.84 19.65,32.73 19.46,32.73 19.34,32.84 19.34,33.29 19.23,33.4 19.04,33.4 18.92,33.29 18.92,32.84 18.81,32.73 18.61,32.73 18.5,32.84 18.5,33.29 18.39,33.4 18.19,33.4 18.08,33.29 18.08,32.84 17.97,32.73 17.77,32.73 17.66,32.84 17.66,33.29 17.55,33.4 17.35,33.4 17.24,33.29 17.24,32.84 17.12,32.73 15.21,32.73 15.1,32.84 15.1,33.29 14.99,33.4 14.79,33.4 14.68,33.29 14.68,32.84 14.57,32.73 14.37,32.73 14.26,32.84 14.26,33.29 14.14,33.4 13.95,33.4 13.84,33.29 13.84,32.84 13.72,32.73 12.82,32.73 12.41,32.32 12.25,32.32 11.36,33.21 11.2,33.21 11.06,33.07 11.06,32.91 11.95,32.02 11.95,31.86 11.59,31.49 11.43,31.49 10.94,31.98 10.77,31.98 10.64,31.85 10.64,31.69 11.13,31.19 11.13,31.03 10.81,30.71 10.65,30.71 9.14,32.22 8.98,32.22 8.84,32.08 8.84,31.92 10.35,30.41 10.35,30.25 10.21,30.12 10.05,30.12 8.54,31.62 8.38,31.62 8.25,31.49 8.25,31.33 9.75,29.82 9.75,29.66 9.34,29.25 v1(7.37,29.25)
  BOTTOM w0.114: v1(7.37,29.25) J7.105 ; v1(48.14,28.5) 48.47,28.5 48.72,28.75 J8.67
DQ24: length 75.6
  TOP w0.114: v1(33.69,33.18) J5.18 35.92,32.12 36.37,31.67 42.97,31.67 45.68,28.97 48.72,28.97 49.97,27.72 53.76,27.72 54.17,27.31 55.64,27.31 v1(56.7,26.25)
  L03_SIG1 w0.114: v1(10.47,36.73) 10.47,34.49 10.76,34.2 11.23,34.2 11.34,34.32 11.34,35.45 11.46,35.56 11.65,35.56 11.76,35.45 11.76,34.32 11.88,34.2 12.07,34.2 12.18,34.32 12.18,35.19 12.3,35.31 12.49,35.31 12.6,35.19 12.6,34.32 12.72,34.2 26.3,34.2 26.42,34.32 26.42,35.19 26.53,35.31 26.72,35.31 26.84,35.19 26.84,34.32 26.95,34.2 27.14,34.2 27.26,34.32 27.26,35.19 27.37,35.31 27.56,35.31 27.68,35.19 27.68,34.32 27.79,34.2 27.99,34.2 28.1,34.32 28.1,35.19 28.21,35.31 28.41,35.31 28.52,35.19 28.52,34.32 28.63,34.2 28.83,34.2 28.94,34.32 28.94,35.19 29.06,35.31 29.25,35.31 29.36,35.19 29.36,34.32 29.48,34.2 29.67,34.2 29.78,34.32 29.78,35.19 29.9,35.31 30.09,35.31 30.2,35.19 30.2,34.32 30.32,34.2 30.57,34.2 30.68,34.32 30.68,35.19 30.8,35.31 30.99,35.31 31.1,35.19 31.1,34.32 31.22,34.2 31.41,34.2 31.52,34.32 31.52,35.19 31.64,35.31 31.83,35.31 31.94,35.19 31.94,34.32 32.06,34.2 32.25,34.2 32.36,34.32 32.36,35.19 32.48,35.31 32.67,35.31 32.78,35.19 32.78,34.32 32.9,34.2 33.53,34.2 33.69,34.04 v1(33.69,33.18)
  BOTTOM w0.114: v1(10.47,36.73) 10.47,37.15 10.57,37.25 J7.74 ; J8.78 v1(56.7,26.25)
DQ25: length 75.8
  TOP w0.114: v1(54.47,27.75) 54.47,28.34 54.07,28.73 49.97,28.73 49.39,29.32 46.01,29.32 44.93,30.4 44.93,30.56 45.33,30.96 45.33,31.12 45.19,31.26 45.03,31.26 44.63,30.86 44.47,30.86 44.33,30.99 44.33,31.15 44.73,31.56 44.73,31.72 44.6,31.86 44.44,31.86 44.03,31.45 43.87,31.45 43.31,32.02 38.84,32.02 38.2,32.66 38.2,35.17 37.66,35.72 J5.20 v1(33.69,35.72)
  L03_SIG1 w0.114: v1(33.69,35.72) 25.89,35.72 25.77,35.6 25.77,34.66 25.66,34.54 25.47,34.54 25.35,34.66 25.35,35.6 25.24,35.72 25.05,35.72 24.93,35.6 24.93,34.66 24.82,34.54 24.63,34.54 24.51,34.66 24.51,35.6 24.4,35.72 24.2,35.72 24.09,35.6 24.09,34.66 23.98,34.54 23.78,34.54 23.67,34.66 23.67,35.6 23.56,35.72 23.36,35.72 23.25,35.6 23.25,34.66 23.13,34.54 22.94,34.54 22.83,34.66 22.83,35.6 22.71,35.72 22.5,35.72 22.38,35.6 22.38,34.66 22.27,34.54 22.08,34.54 21.96,34.66 21.96,35.6 21.85,35.72 21.66,35.72 21.54,35.6 21.54,34.66 21.43,34.54 21.24,34.54 21.12,34.66 21.12,35.6 21.01,35.72 20.82,35.72 20.7,35.6 20.7,34.66 20.59,34.54 20.39,34.54 20.28,34.66 20.28,35.6 20.17,35.72 19.97,35.72 19.86,35.6 19.86,34.66 19.75,34.54 19.55,34.54 19.44,34.66 19.44,35.6 19.33,35.72 19.13,35.72 19.02,35.6 19.02,34.66 18.9,34.54 18.71,34.54 18.6,34.66 18.6,35.6 18.48,35.72 18.29,35.72 18.18,35.6 18.18,34.66 18.06,34.54 17.87,34.54 17.76,34.66 17.76,35.6 17.64,35.72 17.07,35.72 16.12,34.76 15.35,34.76 15.24,34.88 15.24,35.45 15.13,35.56 14.93,35.56 14.82,35.45 14.82,34.88 14.7,34.76 14.51,34.76 14.4,34.88 14.4,35.45 14.28,35.56 14.09,35.56 13.98,35.45 13.98,34.88 13.86,34.76 v1(13.27,34.76)
  BOTTOM w0.114: J7.82 12.79,35.25 v1(13.27,34.76) ; J8.72 v1(54.47,27.75)
DQ26: length 75.7
  TOP w0.114: v1(33.69,38.26) J5.22 38.16,38.26 38.54,37.88 38.54,32.8 38.98,32.36 45.59,32.36 v1(48.2,29.75)
  L04_SIG2 w0.114: v1(4.25,19.74) 4.25,24.96 4.7,25.4 5.38,25.4 5.5,25.51 5.5,26.56 5.61,26.67 5.8,26.67 5.92,26.56 5.92,25.51 6.03,25.4 6.22,25.4 6.34,25.51 6.34,26.56 6.45,26.67 6.64,26.67 6.76,26.56 6.76,25.51 6.87,25.4 7.06,25.4 7.18,25.51 7.18,26.56 7.29,26.67 7.49,26.67 7.6,26.56 7.6,25.51 7.71,25.4 9.39,25.4 9.51,25.51 9.51,26.43 9.62,26.54 9.81,26.54 9.93,26.43 9.93,25.51 10.04,25.4 10.23,25.4 10.35,25.51 10.35,26.43 10.46,26.54 10.66,26.54 10.77,26.43 10.77,25.51 10.88,25.4 14.6,25.4 17.27,28.07 17.27,29.59 25.94,38.26 v1(33.69,38.26)
  BOTTOM w0.114: J7.121 4.34,20.24 4.25,20.15 v1(4.25,19.74) ; J8.63 v1(48.2,29.75)
DQ27: length 75.9
  TOP w0.114: v1(33.69,40.8) J5.24 37.91,40.8 39.4,39.31 47.67,39.31 48.29,38.69 54.52,38.69 v1(56.96,36.25)
  BOTTOM w0.114: J7.104 13.04,29.75 13.09,29.69 13.59,29.69 14.09,30.19 14.09,32.11 15.75,33.78 22.73,33.78 31.62,42.67 41.19,42.67 41.53,42.33 41.53,41.15 41.18,40.8 37.62,40.8 37.51,40.91 37.51,41.8 37.39,41.91 37.2,41.91 37.09,41.8 37.09,41.04 36.97,40.93 36.78,40.93 36.67,41.04 36.67,41.8 36.55,41.91 36.36,41.91 36.25,41.8 36.25,40.91 36.13,40.8 v1(33.69,40.8) ; J8.58 v1(56.96,36.25)
DQ28: length 75.9
  TOP w0.114: v1(31.81,36.73) 31.81,41.47 33.69,43.34 J5.26 37.92,43.34 39.15,44.57 53.11,44.57 v1(53.4,44.86)
  L04_SIG2 w0.114: v1(31.81,36.73) 25.39,36.73 18.03,29.38 18.03,27.3 16.99,26.26 16.99,26.1 17.72,25.37 17.72,25.21 17.58,25.07 17.42,25.07 16.69,25.8 16.53,25.8 16.39,25.66 16.39,25.5 17.12,24.77 17.12,24.61 16.98,24.48 16.82,24.48 16.1,25.2 15.93,25.2 15.76,25.03 15.76,24.87 16.36,24.27 16.36,24.11 16.23,23.97 16.07,23.97 15.47,24.57 15.3,24.57 15.17,24.44 15.17,24.28 15.77,23.68 15.77,23.52 15.63,23.38 15.47,23.38 14.87,23.98 14.71,23.98 14.57,23.84 14.57,23.68 15.17,23.08 15.17,22.92 15.04,22.78 14.88,22.78 14.28,23.38 14.11,23.38 13.78,23.05 v1(13.78,17.74)
  BOTTOM w0.114: J8.38 54.1,41.25 53.4,41.94 v1(53.4,44.86) ; v1(13.78,17.74) 13.02,17.74 12.52,18.24 J7.130
DQ29: length 78
  TOP w0.114: J5.28 v1(33.69,45.88)
  L03_SIG1 w0.114: v1(33.69,45.88) 33.69,48.51 34.07,48.9 37.97,48.9 38.08,49.01 38.08,49.8 38.19,49.91 38.39,49.91 38.5,49.8 38.5,49.01 38.62,48.9 50.41,48.9 52.24,47.07 52.24,29.58 52.58,29.24 55.76,29.24 v1(56.77,30.25)
  BOTTOM w0.114: J7.98 12.74,31.25 15.61,34.12 19.64,34.12 31.4,45.88 v1(33.69,45.88) ; J8.62 v1(56.77,30.25)
DQ30: length 90.5
  TOP w0.114: J5.30 33.81,48.42 30.29,44.89 v1(30.29,37.37)
  L04_SIG2 w0.114: v1(56.7,40.75) 56.42,41.03 54.57,41.03 54.06,41.54 54.06,41.92 54.48,42.34 54.48,42.81 54.09,43.19 46.64,43.19 43.81,40.36 42.39,40.36 39.4,37.37 38.58,37.37 38.47,37.48 38.47,38.62 38.35,38.73 38.16,38.73 38.04,38.62 38.04,37.36 37.93,37.24 37.74,37.24 37.62,37.36 37.62,38.62 37.51,38.73 37.32,38.73 37.2,38.62 37.2,37.36 37.09,37.24 36.9,37.24 36.78,37.36 36.78,38.62 36.67,38.73 36.48,38.73 36.36,38.62 36.36,37.48 36.25,37.37 36.06,37.37 35.94,37.48 35.94,38.62 35.83,38.73 35.64,38.73 35.52,38.62 35.52,37.48 35.41,37.37 35.21,37.37 35.1,37.48 35.1,38.62 34.99,38.73 34.79,38.73 34.68,38.62 34.68,37.48 34.57,37.37 v1(30.29,37.37) 25.54,37.37 17.65,29.49 17.65,27.94 13.14,23.43 v1(13.14,18.24)
  BOTTOM w0.114: v1(13.14,18.24) 12.64,18.74 J7.128 ; J8.40 v1(56.7,40.75)
DQ31: length 78.3
  TOP w0.114: J5.32 v1(33.69,50.96)
  L03_SIG1 w0.114: v1(54.48,29.75) 52.58,31.65 52.58,47.21 48.83,50.96 37.04,50.96 36.93,50.84 36.93,50.03 36.81,49.91 36.62,49.91 36.51,50.03 36.51,50.84 36.39,50.96 36.2,50.96 36.09,50.84 36.09,49.9 35.97,49.78 35.78,49.78 35.67,49.9 35.67,50.84 35.55,50.96 35.36,50.96 35.25,50.84 35.25,49.9 35.13,49.78 34.94,49.78 34.83,49.9 34.83,50.84 34.71,50.96 v1(33.69,50.96)
  BOTTOM w0.114: J8.64 v1(54.48,29.75) ; J7.94 13.25,32.25 15.47,34.46 17.95,34.46 33.69,50.2 v1(33.69,50.96)
I2C_SCL_PPORT: length 66.9
  TOP w0.114: v1(15.78,38.26) J6.22 20,38.26 21.4,36.86 26.73,36.86 27.33,36.27 27.33,23.42 31.88,18.87 56.24,18.87 56.71,19.34 v1(56.71,23.49)
  BOTTOM w0.114: v1(56.71,23.49) 56.44,23.75 J8.88 ; v1(15.78,38.26) 14.29,39.75 J7.64
I2C_SDA_PPORT: length 66.5
  TOP w0.114: v1(56.7,24.25) 53.92,21.47 50.22,21.47 47.97,19.21 32.02,19.21 27.67,23.56 27.67,37.07 26.48,38.26 v1(25.22,38.26) J6.21
  L03_SIG1 w0.114: v1(25.22,38.26) 24.74,38.75 v1(12.83,38.75)
  BOTTOM w0.114: J8.86 v1(56.7,24.25) ; J7.68 v1(12.83,38.75)
I2S-MCLK: length 70.7
  TOP w0.114: v1(15.78,45.88) J6.28 19.88,45.88 21.27,44.48 27.62,44.48 28.76,43.34 28.76,24.52 31.43,21.86 45.18,21.86 45.85,22.53 48.65,22.53 49.39,21.8 50.07,21.8 50.08,21.81 53.07,21.81 v1(54.49,23.23)
  BOTTOM w0.114: J7.62 12.59,40.25 14.03,41.69 14.03,45.5 14.41,45.88 v1(15.78,45.88) ; v1(54.49,23.23) 54.51,23.25 J8.90
I2S_CLK: length 68
  TOP w0.114: J6.25 v1(25.22,43.34) 27.5,43.34 28.36,42.48 28.36,24.44 31.29,21.51 45.32,21.51 45.99,22.19 46.99,22.19 v1(47.43,21.75)
  L03_SIG1 w0.114: v1(25.22,43.34) 24.72,43.85 10.2,43.85 v1(6.6,40.25)
  BOTTOM w0.114: J8.95 v1(47.43,21.75) ; J7.61 v1(6.6,40.25)
I2S_SD: length 75.6
  TOP w0.114: J6.27 v1(25.22,45.88) 28.38,45.88 29.27,44.99 29.27,25.3 32.38,22.2 45.03,22.2 45.71,22.87 49.91,22.87 v1(50.53,22.25)
  L03_SIG1 w0.114: v1(4.25,39.26) 10.25,45.26 24.59,45.26 25.21,45.88 v1(25.22,45.88)
  BOTTOM w0.114: J7.63 4.73,39.75 v1(4.25,39.26) ; J8.93 v1(50.53,22.25)
I2S_WP: length 67.2
  TOP w0.114: v1(46.42,21.75) 44.22,19.55 32.16,19.55 28.02,23.7 28.02,41.04 26.99,42.07 21.27,42.07 20,43.34 J6.26 v1(15.78,43.34)
  L03_SIG1 w0.114: v1(6.6,38.75) 11.2,43.34 v1(15.78,43.34)
  BOTTOM w0.114: J7.67 v1(6.6,38.75) ; v1(46.42,21.75) 47.42,22.75 J8.91
INT_N_CTL15: length 53.6
  TOP w0.114: J6.17 v1(25.22,33.18)
  L04_SIG2 w0.114: v1(53.44,38.13) 52.64,38.13 51.09,39.69 50.47,39.69 50.19,39.97 47.14,39.97 46.16,38.99 43.07,38.99 38.18,34.11 26.15,34.11 v1(25.22,33.18)
  BOTTOM w0.114: J7.112 12.49,27.75 12.97,27.26 20.95,27.26 25.21,31.53 25.21,33.16 v1(25.22,33.18) ; v1(53.44,38.13) 53.82,37.75 J8.52
PCLK: length 104.9
  TOP w0.114: J5.34 37.92,53.5 39.03,54.61 44.83,54.61 55.75,43.69 55.75,40.7 v1(56.7,39.75)
  L03_SIG1 w0.114: v1(56.7,39.75) 57.74,38.71 57.74,26.24 56.14,24.64 56.12,24.64 56.09,24.64 53.72,24.64 41.66,12.57 30.23,12.57 24.1,6.45 6.89,6.45 v1(6.59,6.74)
  BOTTOM w0.114: J7.175 v1(6.59,6.74) ; J8.44 v1(56.7,39.75)
PMODE0_CON: length 66.5
  TOP w0.114: J6.14 v1(15.78,28.1)
  L03_SIG1 w0.114: v1(15.78,28.1) 15.78,25.43 10.41,20.06 10.41,20.04 10.4,20.04 v1(10.4,16.74)
  L04_SIG2 w0.114: v1(15.78,28.1) 16.89,29.21 16.89,31.11 25.18,39.4 39.48,39.4 41.31,41.24 43.43,41.24 45.72,43.53 54.26,43.53 54.86,42.93 54.86,42.11 v1(54.49,41.74)
  BOTTOM w0.114: v1(10.4,16.74) 10.9,17.24 J7.134 ; v1(54.49,41.74) 54.85,41.74 54.86,41.75 J8.36
PMODE1_CON: length 62.2
  TOP w0.114: J6.15 v1(25.22,30.64)
  BOTTOM w0.114: J8.46 53.38,39.25 53,38.87 53,37.1 52.77,36.86 51.63,36.86 51.24,36.48 51.24,33.18 50.61,32.54 27.13,32.54 v1(25.22,30.64) 21.47,26.89 14.31,26.89 12.7,25.27 10.67,25.27 9.4,26.54 7.62,26.54 6.42,27.75 J7.111
PMODE2_CON: length 67.8
  TOP w0.114: v1(14.03,14.51) 14.36,14.83 14.36,29.22 v1(15.78,30.64) J6.16
  L04_SIG2 w0.114: v1(15.78,30.64) 17,31.86 17.01,31.86 24.9,39.75 39.33,39.75 41.27,41.69 43.37,41.69 45.78,44.1 v1(54.04,44.1)
  BOTTOM w0.114: J7.148 13.26,13.74 v1(14.03,14.51) ; J8.30 54.51,43.25 54.04,43.72 v1(54.04,44.1)
RESET_N_CON: length 68.9
  TOP w0.114: J6.18 v1(15.78,33.18)
  L04_SIG2 w0.114: v1(15.78,33.18) 14.63,34.33 3.97,34.33 3.49,33.85 3.49,18.95 4.18,18.27 v1(4.18,18.24)
  BOTTOM w0.114: v1(4.18,18.24) 4.68,18.74 J7.127 ; v1(15.78,33.18) 23.15,33.18 27.79,37.82 43.08,37.82 45.15,35.75 J8.59
VIO1_HDR: length 60.7
  L03_SIG1 w0.508: v1(19.2,55.28) 22.2,52.28 48.51,52.28 v1(50.53,50.26)
  L04_SIG2 w0.508: v1(56.7,49.76) 56.2,50.26 v1(54.47,50.26) v1(50.53,50.26) 48.8,50.26 v1(48.3,49.76)
  BOTTOM w0.254: v1(51.18,15.49) 50.43,16.24 J8.117 47.61,16.24 v1(46.61,15.24) ; J8.119 48.26,15.74 v1(47.88,15.37) ; J8.3 v1(48.3,49.76) ; J8.2 v1(54.47,50.26) ; J8.1 v1(50.53,50.26) ; J8.4 v1(56.7,49.76) ; 54.34,16.24 54.1,16 v1(54.1,15.49) 54.35,15.74 J8.120 56.67,15.74 v1(56.92,15.49) 56.92,15.98 56.66,16.24 J8.118 54.34,16.24
  vias: v1(16.66,59.21) v1(16.66,57.94) v1(16.66,56.55) v1(16.66,55.28) v1(17.93,59.21) v1(17.93,57.94) v1(17.93,56.55) v1(17.93,55.28) v1(19.2,59.21) v1(19.2,57.94) v1(19.2,56.55)

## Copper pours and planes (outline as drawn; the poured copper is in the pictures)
GND2 on TOP: 0.44,65.44 32.96,65.44 32.96,54.86 57.98,54.86 57.98,11.05 32.96,11.05 32.96,0.54 32.99,0.51 0.44,0.51 ; 9 cut-outs
GND2 on BOTTOM: 0.44,65.44 32.96,65.44 32.96,54.86 57.98,54.86 57.98,11.05 32.96,11.05 32.96,0.54 32.99,0.51 0.44,0.51 ; 3 cut-outs
GND2 on L02_GND1: 0.44,65.44 32.96,65.44 32.96,54.86 57.98,54.86 57.98,11.05 32.96,11.05 32.96,0.54 32.99,0.51 0.44,0.51
GND2 on L03_SIG1: 0.44,65.44 32.96,65.44 32.96,54.86 57.98,54.86 57.98,11.05 32.96,11.05 32.96,0.54 32.99,0.51 0.44,0.51 ; 18 cut-outs
GND2 on L04_SIG2: 0.44,65.44 32.96,65.44 32.96,54.86 57.98,54.86 57.98,11.05 32.96,11.05 32.96,0.54 32.99,0.51 0.44,0.51 ; 20 cut-outs
V5P0_HDR on TOP (solid shape): 25.01,59.59 25.01,47.66 24.75,47.4 21.07,47.4 20.81,47.66 20.81,59.59 21.07,59.85 24.75,59.85
V5P0_HDR on L05_PWR1: 20.38,64.8 20.51,64.93 32.32,64.93 32.45,64.8 32.45,53.88 57.47,53.88 57.47,16.67 57.34,16.54 20.51,16.54 20.38,16.67
VIO1_HDR on TOP (solid shape): 20,59.59 20,47.66 19.75,47.4 16.07,47.4 15.81,47.66 15.81,59.59 16.07,59.85 19.75,59.85
VIO1_HDR on L05_PWR1: 19.75,64.93 19.88,64.8 19.88,16.16 20,16.03 57.34,16.03 57.47,15.91 57.47,12.1 32.45,12.1 32.45,0.92 0.95,0.92 0.95,64.93

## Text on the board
Ref Des/Silkscreen Bottom: 1 | 59 | 61 | 121 | 119 | 179 | 2 | 62 | 60 | 120 | 122 | 180 | www.agile-sdr-solutions.com
User.Comments: - | D | DESIGNED BY : | DATE | UNLESS OTHERWISE SPECIFIED | ALL DIMENSIONS ARE IN | INCHES | MILLIMETERS | SIZE | SCALE | PART NUMBER | 1:1 | ASSMB NO- | -XXXXXXXXXX | SHEET | 1  OF | 1.0 | REV | 1 | 14/06/2013 | AgileSolutions | DRAWING TITLE | AGILE SOLUTIONS | X
